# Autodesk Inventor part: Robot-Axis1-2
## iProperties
Shininess: 21.0
Length Units: 11269
Angle Units: 11279
Time Units: 11290
Mass Units: 11283
Length Display Precision: 3
Angle Display Precision: 2
Created: 2001-08
Part Number: Robot-Axis1-2
Document SubType Name: ﾓﾃﾞﾘﾝｸﾞ
Designer: Administrator
Density: 1 g/cm^3
Density: 0.0
Volumn: 0.0
Area: 0.0
PropertySet Name: Model Information
Control State: 0
Master: False
Checked Out: False
Author: Administrator
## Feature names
1. Extrusion1
2. Extrusion3
3. Extrusion4
4. Chamfer [Fillet]
5. Extrusion6
6. Mirror3
7. Shell1
8. Hole1
9. Hole2
